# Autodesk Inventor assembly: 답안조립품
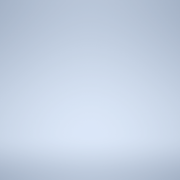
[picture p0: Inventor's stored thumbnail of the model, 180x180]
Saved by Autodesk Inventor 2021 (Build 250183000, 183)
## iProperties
Created: 2022-08
Part Number: 답안조립품
Document SubType Name: Assembly
Designer: Owner
Author: Owner
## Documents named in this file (1)
- C:\Users\Owner\Desktop\720810V1011\답안조립품.iam
